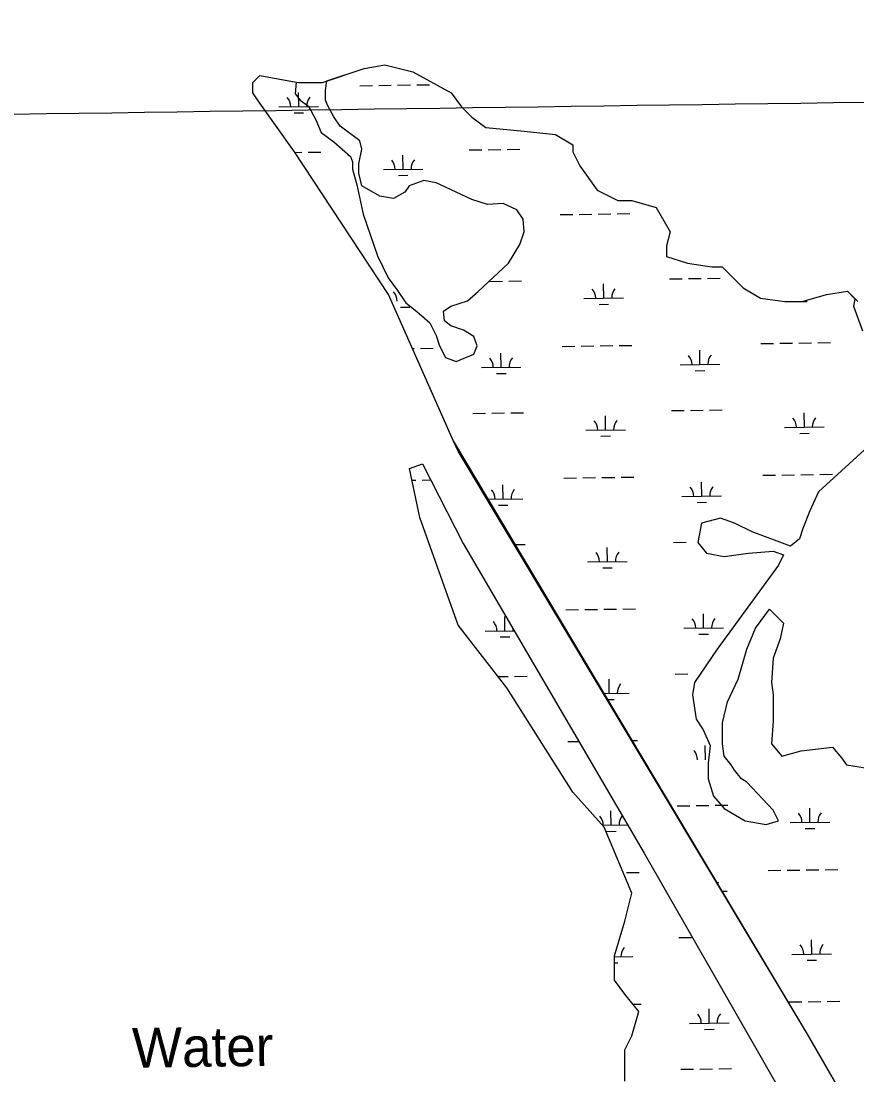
# Model space of a CAD drawing. Extents: x 3775218 to 3813389, y 343470 to 369318.
# Drawn here: x 3791487 to 3793598, y 352694 to 355355 of the extents above; entities that cross this region are included whole.
import ezdxf

# ---------------------------------------------------------------- set-up
doc = ezdxf.new("R2010")
doc.units = 0
for name, color, linetype in [('V-GRID-MAJR', 7, 'Continuous'), ('V-RIVR-IDEN', 7, 'Continuous'), ('V-TOPO-SHOR', 7, 'Continuous'), ('V-WETL-SWMP', 7, 'Continuous')]:
    doc.layers.add(name, color=color, linetype=linetype)

msp = doc.modelspace()

# ---------------------------------------------------------------- linework, layer by layer
at = {"layer": 'V-GRID-MAJR'}
msp.add_spline([(3779369.4, 354952.8), (3784672.7, 355025.7), (3789975.9, 355099.3), (3795279.1, 355173.8), (3800582.3, 355249), (3805885.5, 355325), (3811188.7, 355401.7)], degree=3, dxfattribs=at)
at = {"layer": 'V-TOPO-SHOR'}
for p, q in [((3792353.6, 355235.4), (3792406.2, 355244.2)), ((3792406.2, 355244.2), (3792476.5, 355226.6)), ((3792072.6, 355200.2), (3792090.1, 355217.8)), ((3792090.1, 355217.8), (3792182, 355201.1)), ((3792259.6, 355204.1), (3792353.6, 355235.4)), ((3792476.5, 355226.6), (3792573.1, 355173.9)), ((3792072.6, 355173.9), (3792072.6, 355200.2)), ((3792090.1, 355147.5), (3792072.6, 355173.9)), ((3792573.1, 355173.9), (3792599.4, 355138.7)), ((3792177.9, 355024.5), (3792090.1, 355147.5)), ((3792599.4, 355138.7), (3792625.8, 355112.4)), ((3792625.8, 355112.4), (3792660.9, 355086)), ((3792660.9, 355086), (3792757.5, 355077.2)), ((3792757.5, 355077.2), (3792836.5, 355068.4)), ((3792836.5, 355068.4), (3792880.4, 355042.1)), ((3792880.4, 355042.1), (3792880.4, 355024.5)), ((3792415, 354664.3), (3792177.9, 355024.5)), ((3792880.4, 355024.5), (3792898, 354989.4)), ((3792898, 354989.4), (3792941.9, 354927.9)), ((3792941.9, 354927.9), (3792994.5, 354901.5)), ((3792994.5, 354901.5), (3793029.7, 354901.5)), ((3793029.7, 354901.5), (3793091.1, 354883.9)), ((3793091.1, 354883.9), (3793126.3, 354822.4)), ((3793126.3, 354822.4), (3793117.5, 354787.3)), ((3793117.5, 354787.3), (3793117.5, 354760.9)), ((3793117.5, 354760.9), (3793170.2, 354743.3)), ((3793170.2, 354743.3), (3793231.6, 354734.6)), ((3793231.6, 354734.6), (3793258, 354734.6)), ((3793258, 354734.6), (3793310.6, 354681.8)), ((3792578.7, 354295.7), (3792415, 354664.3)), ((3793310.6, 354681.8), (3793354.6, 354655.5)), ((3793459.9, 354646.7), (3793521.4, 354664.3)), ((3793521.4, 354664.3), (3793574.1, 354673)), ((3793574.1, 354673), (3793593.1, 354654)), ((3793354.6, 354655.5), (3793416, 354646.7)), ((3793416, 354646.7), (3793459.9, 354646.7)), ((3792579.1, 354294.8), (3792578.5, 354296.1)), ((3793473.1, 352797.1), (3792579.1, 354294.8)), ((3792467.7, 354224.9), (3792501.3, 354236.9)), ((3792501.3, 354236.9), (3792603.8, 354036)), ((3792494, 354101.9), (3792467.7, 354224.9)), ((3792590.6, 353829.5), (3792494, 354101.9)), ((3792603.8, 354036), (3793060.4, 353254)), ((3792713.6, 353671.4), (3792590.6, 353829.5)), ((3792880.4, 353407.8), (3792713.6, 353671.4)), ((3792959.4, 353319.9), (3792880.4, 353407.8)), ((3793029.7, 353152.9), (3792959.4, 353319.9)), ((3793060.4, 353254), (3793438, 352595)), ((3793012.1, 353082.6), (3793029.7, 353152.9)), ((3792985.8, 352994.8), (3793009.4, 353073.5)), ((3793009.4, 353073.5), (3793012.1, 353082.6)), ((3792985.8, 352933.3), (3792985.8, 352994.8)), ((3793012.1, 352898.1), (3792985.8, 352933.3)), ((3793047.2, 352854.2), (3793012.1, 352898.1)), ((3793029.7, 352792.7), (3793047.2, 352854.2)), ((3794351.2, 351277), (3793473.1, 352797.1)), ((3793012.1, 352757.5), (3793029.7, 352792.7)), ((3793012.1, 352678.5), (3793012.1, 352757.5))]:
    msp.add_line(p, q, dxfattribs=at)
for points in [[(3792182, 355201.1), (3792179.1, 355171.4), (3792192.3, 355155.6), (3792213.4, 355139.7), (3792231.9, 355105.4), (3792245.1, 355073.7), (3792276.8, 355049.9), (3792319, 355013), (3792324.3, 354999.8), (3792324.3, 354981.3), (3792334.9, 354941.6), (3792350.7, 354867.7), (3792387.7, 354762.1), (3792414.1, 354706.6), (3792437.9, 354674.9), (3792459, 354643.2), (3792482.8, 354624.7), (3792498.6, 354611.5), (3792519.8, 354593), (3792535.6, 354561.3), (3792543.5, 354534.9), (3792559.4, 354505.9), (3792585.8, 354495.3), (3792630.7, 354513.8), (3792638.6, 354534.9), (3792630.7, 354558.7), (3792604.3, 354574.5), (3792572.6, 354585.1), (3792556.7, 354598.3), (3792554.1, 354622.1), (3792572.6, 354635.3), (3792614.8, 354648.5), (3792641.2, 354672.3), (3792717.8, 354743.6), (3792746.9, 354791.1), (3792757.5, 354822.8), (3792754.8, 354854.5), (3792739, 354878.3), (3792704.6, 354894.1), (3792665, 354891.5), (3792625.4, 354904.7), (3792546.2, 354941.6), (3792535.6, 354946.9), (3792503.9, 354952.2), (3792466.9, 354939), (3792456.4, 354923.2), (3792427.3, 354907.3), (3792393, 354912.6), (3792348.1, 354939), (3792340.2, 354970.7), (3792340.2, 354994.5), (3792348.1, 355031.4), (3792342.8, 355052.6), (3792292.6, 355089.5), (3792276.8, 355113.3), (3792260.9, 355142.4), (3792255.7, 355155.6), (3792255.7, 355179.3), (3792259.6, 355204.1)], [(3793593.1, 354654), (3793589.6, 354635.1), (3793611.7, 354573.2)], [(3793655.9, 354308), (3793501.2, 354166.5), (3793479.1, 354117.9), (3793461.4, 354073.7), (3793452.6, 354047.2), (3793430.5, 354029.5), (3793333.2, 354064.9), (3793289, 354087), (3793253.7, 354100.2), (3793205.1, 354087), (3793196.2, 354038.4), (3793218.3, 354011.8), (3793262.5, 354003), (3793324.4, 354011.8), (3793386.3, 354016.3), (3793412.8, 354007.4), (3793399.5, 353980.9), (3793244.8, 353768.7), (3793187.4, 353684.8), (3793183, 353653.8), (3793191.8, 353591.9), (3793209.5, 353565.4), (3793227.2, 353525.6), (3793222.7, 353481.4), (3793222.7, 353441.7), (3793236, 353397.5), (3793262.5, 353366.5), (3793315.6, 353335.6), (3793368.6, 353326.7), (3793399.5, 353335.6), (3793386.3, 353362.1), (3793320, 353432.8), (3793306.7, 353441.7), (3793289, 353463.8), (3793280.2, 353477), (3793262.5, 353499.1), (3793258.1, 353530.1), (3793258.1, 353583.1), (3793271.4, 353636.1), (3793297.9, 353693.6), (3793320, 353768.7), (3793342.1, 353821.8), (3793377.4, 353870.4), (3793412.8, 353835), (3793404, 353795.3), (3793386.3, 353746.6), (3793381.9, 353684.8), (3793386.3, 353653.8), (3793386.3, 353587.5), (3793381.9, 353530.1), (3793408.4, 353499.1), (3793457, 353512.4), (3793536.6, 353521.2), (3793558.7, 353494.7), (3793571.9, 353477), (3793625, 353468.2)]]:
    msp.add_lwpolyline(points, dxfattribs=at)
at = {"layer": 'V-WETL-SWMP'}
for p, q in [((3792342.3, 355191.8), (3792374.3, 355192.3)), ((3792390.3, 355192.5), (3792422.2, 355192.9)), ((3792438.2, 355193.2), (3792470.2, 355193.6)), ((3792486.2, 355193.8), (3792518.2, 355194.3)), ((3792188.4, 355138.9), (3792187.9, 355174.9)), ((3792138.4, 355138.2), (3792238.4, 355139.6)), ((3792176.6, 355123.3), (3792200.6, 355123.6)), ((3792618.5, 355029.5), (3792650.5, 355030)), ((3792666.5, 355030.2), (3792698.5, 355030.7)), ((3792714.5, 355030.9), (3792746.5, 355031.3)), ((3792178.7, 355023.3), (3792196.6, 355023.6)), ((3792212.6, 355023.8), (3792244.6, 355024.2)), ((3792452.1, 354980.7), (3792451.6, 355016.7)), ((3792402.1, 354980), (3792502.1, 354981.4)), ((3792440.3, 354965.1), (3792464.3, 354965.5)), ((3792848.8, 354866.3), (3792880.8, 354866.7)), ((3792896.8, 354866.9), (3792928.8, 354867.4)), ((3792944.8, 354867.6), (3792976.8, 354868.1)), ((3792992.8, 354868.3), (3793024.8, 354868.7)), ((3792671.2, 354697.6), (3792703.2, 354698)), ((3792719.2, 354698.2), (3792751.2, 354698.7)), ((3792958.6, 354655.2), (3792958.1, 354691.2)), ((3793125, 354704), (3793157, 354704.4)), ((3793173, 354704.6), (3793205, 354705.1)), ((3793221, 354705.3), (3793253, 354705.8)), ((3792445, 354632.5), (3792469, 354632.8)), ((3792908.6, 354654.5), (3793008.6, 354655.9)), ((3792946.9, 354639.6), (3792970.9, 354639.9)), ((3793448.7, 354646.7), (3793450.4, 354646.7)), ((3793460.4, 354646.8), (3793472.7, 354647)), ((3792475.4, 354528.3), (3792479.6, 354528.3)), ((3792495.6, 354528.6), (3792527.6, 354529)), ((3792853.5, 354533.6), (3792885.5, 354534.1)), ((3792901.5, 354534.3), (3792933.5, 354534.7)), ((3792949.5, 354535), (3792981.5, 354535.4)), ((3792997.5, 354535.6), (3793029.5, 354536.1)), ((3793201.5, 354487.8), (3793201, 354523.8)), ((3793355.4, 354540.7), (3793387.4, 354541.1)), ((3793403.4, 354541.4), (3793435.4, 354541.8)), ((3793451.4, 354542), (3793483.3, 354542.5)), ((3793499.3, 354542.7), (3793531.3, 354543.2)), ((3792699.6, 354480.7), (3792699.1, 354516.7)), ((3792649.6, 354480), (3792749.6, 354481.4)), ((3793151.5, 354487.1), (3793251.5, 354488.5)), ((3793189.7, 354472.2), (3793213.7, 354472.5)), ((3792687.9, 354465.1), (3792711.9, 354465.4)), ((3792627.9, 354364.2), (3792659.9, 354364.7)), ((3792675.9, 354364.9), (3792707.9, 354365.4)), ((3792723.9, 354365.6), (3792755.9, 354366)), ((3793129.7, 354371.3), (3793161.7, 354371.8)), ((3793177.7, 354372), (3793209.7, 354372.4)), ((3793225.7, 354372.7), (3793257.7, 354373.1)), ((3793465.2, 354329.6), (3793464.7, 354365.6)), ((3792963.3, 354322.5), (3792962.8, 354358.5)), ((3792913.3, 354321.8), (3793013.3, 354323.2)), ((3793415.2, 354328.9), (3793515.2, 354330.3)), ((3793453.4, 354314), (3793477.4, 354314.4)), ((3792951.6, 354306.9), (3792975.6, 354307.3)), ((3792467.7, 354224.9), (3792501.3, 354236.9)), ((3792501.3, 354236.9), (3792603.8, 354036)), ((3792494, 354101.9), (3792467.7, 354224.9)), ((3793360.1, 354208.1), (3793392.1, 354208.5)), ((3793408, 354208.7), (3793440, 354209.2)), ((3793456, 354209.4), (3793488, 354209.9)), ((3793504, 354210.1), (3793536, 354210.5)), ((3792474, 354195.5), (3792484.3, 354195.7)), ((3792500.3, 354195.9), (3792522.1, 354196.2)), ((3792704.3, 354148.1), (3792703.8, 354184)), ((3792858.2, 354201), (3792890.2, 354201.4)), ((3792906.2, 354201.6), (3792938.2, 354202.1)), ((3792954.2, 354202.3), (3792986.2, 354202.8)), ((3793002.2, 354203), (3793034.2, 354203.5)), ((3793206.2, 354155.1), (3793205.7, 354191.1)), ((3793156.2, 354154.4), (3793256.2, 354155.8)), ((3792663.4, 354147.5), (3792754.3, 354148.8)), ((3792692.6, 354132.5), (3792716.6, 354132.8)), ((3793194.4, 354139.5), (3793218.4, 354139.9)), ((3792590.6, 353829.5), (3792494, 354101.9)), ((3792603.8, 354036), (3793060.4, 353254)), ((3792732, 354033), (3792760.6, 354033.4)), ((3792968, 353989.9), (3792967.5, 354025.9)), ((3793134.4, 354038.7), (3793166.4, 354039.1)), ((3792918, 353989.2), (3793018, 353990.6)), ((3792956.2, 353974.3), (3792980.2, 353974.6)), ((3792862.9, 353868.3), (3792894.9, 353868.8)), ((3792910.9, 353869), (3792942.9, 353869.5)), ((3792958.9, 353869.7), (3792990.9, 353870.1)), ((3793006.9, 353870.4), (3793038.9, 353870.8)), ((3793210.9, 353822.5), (3793210.4, 353858.5)), ((3792709, 353815.4), (3792708.5, 353851.4)), ((3792713.6, 353671.4), (3792590.6, 353829.5)), ((3792659, 353814.7), (3792732.4, 353815.7)), ((3793160.9, 353821.8), (3793260.9, 353823.2)), ((3793199.1, 353806.9), (3793223.1, 353807.2)), ((3792697.2, 353799.8), (3792721.2, 353800.1)), ((3792691.5, 353699.7), (3792717.2, 353700.1)), ((3792733.2, 353700.3), (3792765.2, 353700.8)), ((3793139.1, 353706), (3793171.1, 353706.5)), ((3792972.7, 353657.3), (3792972.2, 353693.2)), ((3792880.4, 353407.8), (3792713.6, 353671.4)), ((3792957.5, 353657), (3793022.7, 353658)), ((3792966.6, 353641.7), (3792984.9, 353642)), ((3792867.6, 353535.7), (3792895.7, 353536.1)), ((3793028.9, 353538), (3793043.6, 353538.2)), ((3793215.6, 353489.8), (3793215.1, 353525.8)), ((3792959.4, 353319.9), (3792880.4, 353407.8)), ((3792977.4, 353324.6), (3792976.9, 353360.6)), ((3793143.8, 353373.4), (3793175.8, 353373.8)), ((3793191.8, 353374.1), (3793223.8, 353374.5)), ((3793239.8, 353374.7), (3793271.8, 353375.2)), ((3793479.3, 353331.7), (3793478.8, 353367.7)), ((3793429.3, 353331), (3793529.3, 353332.4)), ((3792955.5, 353324.3), (3793018.8, 353325.2)), ((3793029.7, 353152.9), (3792959.4, 353319.9)), ((3792965.6, 353309), (3792989.6, 353309.4)), ((3793467.5, 353316.1), (3793491.5, 353316.4)), ((3793060.4, 353254), (3793438, 352595)), ((3793016.3, 353205.1), (3793048.3, 353205.5)), ((3793374.1, 353210.1), (3793406.1, 353210.6)), ((3793422.1, 353210.8), (3793454.1, 353211.3)), ((3793470.1, 353211.5), (3793502.1, 353211.9)), ((3793518.1, 353212.2), (3793550.1, 353212.6)), ((3793012.1, 353082.6), (3793029.7, 353152.9)), ((3793256.9, 353157.7), (3793270.3, 353157.9)), ((3792985.8, 352994.8), (3793009.4, 353073.5)), ((3793009.4, 353073.5), (3793012.1, 353082.6)), ((3793148.5, 353040.8), (3793180.5, 353041.2)), ((3793484, 352999), (3793483.5, 353035)), ((3792985.8, 352933.3), (3792985.8, 352994.8)), ((3792985.8, 352992), (3793032.1, 352992.7)), ((3793434, 352998.3), (3793534, 352999.8)), ((3793472.2, 352983.5), (3793496.2, 352983.8)), ((3792985.8, 352976.6), (3792994.3, 352976.7)), ((3793012.1, 352898.1), (3792985.8, 352933.3)), ((3793047.2, 352854.2), (3793012.1, 352898.1)), ((3793426.8, 352878.2), (3793458.8, 352878.6)), ((3793474.8, 352878.8), (3793506.8, 352879.3)), ((3793522.8, 352879.5), (3793554.8, 352880)), ((3793029.7, 352792.7), (3793047.2, 352854.2)), ((3793032.5, 352872.6), (3793053, 352872.9)), ((3793225, 352824.6), (3793224.5, 352860.6)), ((3793175, 352823.9), (3793275, 352825.3)), ((3793213.2, 352809), (3793237.2, 352809.3)), ((3793012.1, 352757.5), (3793029.7, 352792.7)), ((3793012.1, 352678.5), (3793012.1, 352757.5)), ((3793153.2, 352708.1), (3793185.2, 352708.6)), ((3793201.2, 352708.8), (3793233.2, 352709.2)), ((3793249.2, 352709.5), (3793281.2, 352709.9))]:
    msp.add_line(p, q, dxfattribs=at)
msp.add_lwpolyline([(3794351.2, 351277), (3793473.1, 352797.1), (3792590.6, 354268.9), (3792579.3, 354294.4), (3792415, 354664.3), (3792177.9, 355024.5), (3792090.1, 355147.5), (3792072.6, 355173.9), (3792072.6, 355200.2), (3792090.1, 355217.8), (3792186.7, 355200.2), (3792248.2, 355200.2), (3792353.6, 355235.4), (3792406.2, 355244.2), (3792476.5, 355226.6), (3792573.1, 355173.9), (3792599.4, 355138.7), (3792625.8, 355112.4), (3792660.9, 355086), (3792757.5, 355077.2), (3792836.5, 355068.4), (3792880.4, 355042.1), (3792880.4, 355024.5), (3792898, 354989.4), (3792941.9, 354927.9), (3792994.5, 354901.5), (3793029.7, 354901.5), (3793091.1, 354883.9), (3793126.3, 354822.4), (3793117.5, 354787.3), (3793117.5, 354760.9), (3793170.2, 354743.3), (3793231.6, 354734.6), (3793258, 354734.6), (3793310.6, 354681.8), (3793354.6, 354655.5), (3793416, 354646.7), (3793459.9, 354646.7), (3793521.4, 354664.3), (3793574.1, 354673), (3793600.4, 354646.7)], dxfattribs=at)
for centre, start, end in [((3792243.6, 355140.2), 140.0365, 181.5802), ((3792133.2, 355138.6), 0.0365, 41.5802), ((3792396.8, 354980.4), 0.0365, 41.5802), ((3792507.3, 354982), 140.0365, 181.5802), ((3792401.5, 354647.8), 0.0365, 41.5802), ((3792903.4, 354654.9), 0.0365, 41.5802), ((3793013.9, 354656.4), 140.0365, 181.5802), ((3792644.4, 354480.4), 0.0365, 41.5802), ((3792754.9, 354481.9), 140.0365, 181.5802), ((3793146.3, 354487.5), 0.0365, 41.5802), ((3793256.7, 354489), 140.0365, 181.5802), ((3792908.1, 354322.2), 0.0365, 41.5802), ((3793018.6, 354323.8), 140.0365, 181.5802), ((3793409.9, 354329.3), 0.0365, 41.5802), ((3793520.4, 354330.9), 140.0365, 181.5802), ((3793150.9, 354154.8), 0.0365, 41.5802), ((3793261.4, 354156.4), 140.0365, 181.5802), ((3792649.1, 354147.7), 0.0365, 41.5802), ((3792759.6, 354149.3), 140.0365, 181.5802), ((3792912.8, 353989.6), 0.0365, 41.5802), ((3793023.3, 353991.1), 140.0365, 181.5802), ((3792653.8, 353815.1), 0.0365, 41.5802), ((3793155.6, 353822.2), 0.0365, 41.5802), ((3793266.1, 353823.7), 140.0365, 181.5802), ((3792764.3, 353816.7), 172.7932, 181.5802), ((3792917.5, 353656.9), 17.9721, 41.5802), ((3793028, 353658.5), 140.0365, 181.5802), ((3793160.3, 353489.5), 0.0365, 41.5802), ((3793424, 353331.4), 0.0365, 41.5802), ((3793534.5, 353332.9), 140.0365, 181.5802), ((3792922.2, 353324.3), 0.0365, 41.5802), ((3793032.6, 353325.9), 140.6552, 181.5802), ((3793275.5, 353158.5), 140.0365, 148.6264), ((3793037.3, 352993.2), 140.0365, 181.5802), ((3793428.7, 352998.7), 0.0365, 41.5802), ((3793539.2, 353000.3), 140.0365, 181.5802), ((3793169.7, 352824.3), 0.0365, 41.5802), ((3793280.2, 352825.8), 140.0365, 181.5802)]:
    msp.add_arc(centre, 35.2, start, end, dxfattribs=at)

# ---------------------------------------------------------------- texts
at = {"layer": 'V-RIVR-IDEN'}
msp.add_text('Water', height=100, rotation=0.7588, dxfattribs=at).set_placement((3791768.1, 352712.2))

doc.saveas('drawing.dxf')
